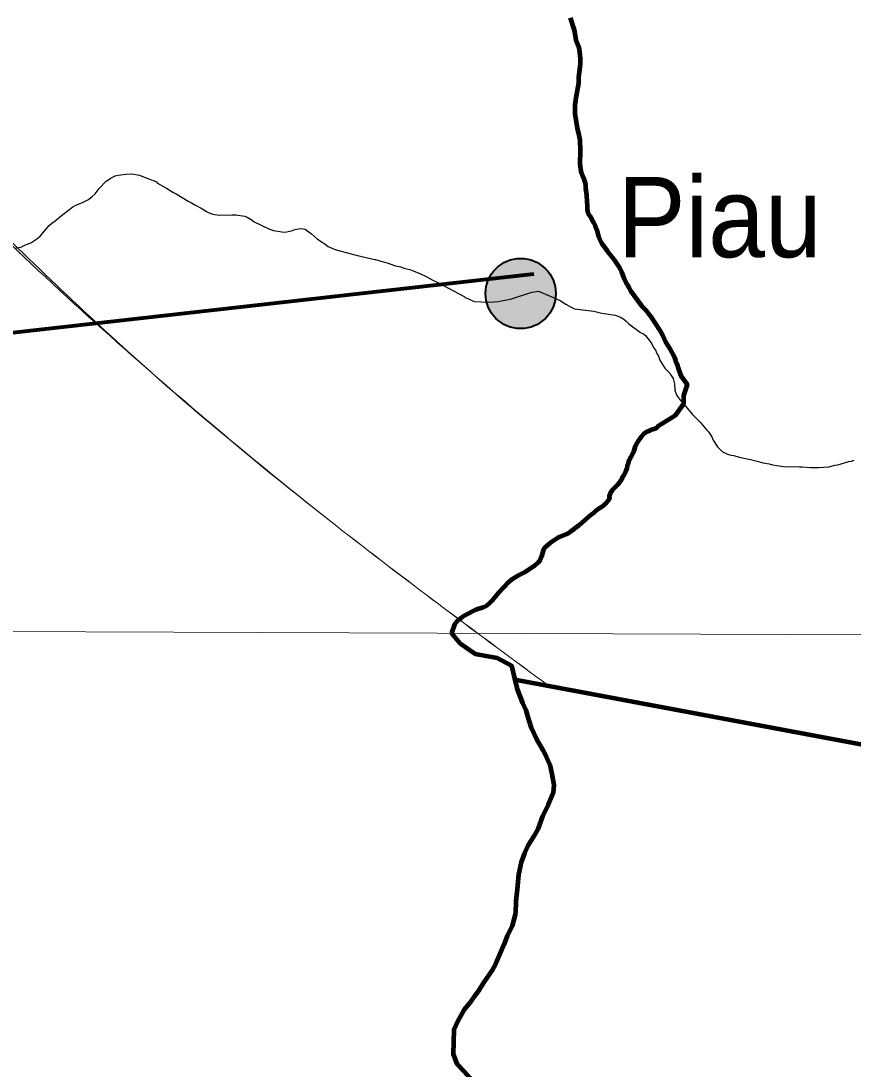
# Model space of a CAD drawing. Extents: x 553962 to 842807, y 8883888 to 9032388.
# Drawn here: x 642715 to 647901, y 8946863 to 8953394 of the extents above; entities that cross this region are included whole.
import ezdxf

# ---------------------------------------------------------------- set-up
doc = ezdxf.new("R2010")
doc.units = 0
doc.header["$LTSCALE"] = 200
doc.linetypes.add('DASH_DOUBLE_DOT', pattern=[9.2, 5, -1.2, 0.3, -1.2, 0.3, -1.2])
for name, color, linetype, lineweight in [('1', 7, 'Continuous', 13), ('11', 7, 'DASH_DOUBLE_DOT', 106), ('12', 7, 'Continuous', 25), ('24', 7, 'Continuous', 25), ('28', 7, 'Continuous', 40), ('41', 7, 'Continuous', 40), ('57', 7, 'Continuous', 13), ('9', 7, 'Continuous', 90)]:
    doc.layers.add(name, color=color, linetype=linetype, lineweight=lineweight)

msp = doc.modelspace()

# ---------------------------------------------------------------- hatches: boundary and pattern name
at = {"layer": '41'}
msp.add_hatch(color=256, dxfattribs=at).paths.add_polyline_path([(646048.1, 8951695.6, 1), (645610.5, 8951695.6, 1)])

# ---------------------------------------------------------------- linework, layer by layer
at = {"layer": '1'}
msp.add_line((565315.3, 8949866.8), (791497.7, 8949052.2), dxfattribs=at)
at = {"layer": '11'}
for points in [[(646137.1, 8953413.1), (646163.8, 8953336.6), (646173.3, 8953276.2), (646189.2, 8953237.6), (646194.5, 8953218.3), (646195.7, 8953199.1), (646201, 8953160.5), (646200.1, 8953124.6), (646189.3, 8953044.8), (646189.1, 8953005.5), (646173, 8952915), (646166.9, 8952872.1), (646167.8, 8952832.8), (646166.9, 8952813.5), (646183.8, 8952715.8), (646190.6, 8952691.8), (646197.6, 8952651.5), (646199.9, 8952587.2), (646199, 8952500.7), (646204.9, 8952458.4), (646221.6, 8952416.4), (646234, 8952374.3), (646233.3, 8952352.9), (646239.6, 8952309.2), (646240.8, 8952267.2), (646243.7, 8952245.8), (646242.9, 8952224.4), (646246, 8952203.9), (646250.1, 8952197.4), (646252.6, 8952188.8), (646256.5, 8952186.2), (646257.9, 8952182.2), (646261.2, 8952179.2), (646263.3, 8952172.7), (646263.3, 8952172.7)], [(646263.3, 8952172.7), (646267.7, 8952169.4), (646271.2, 8952159.2), (646283.8, 8952137.9), (646294.2, 8952117.2), (646303.6, 8952093.2), (646314.2, 8952051.4), (646322.1, 8952031.6), (646333.3, 8952009.5), (646371.8, 8951955.7), (646409.8, 8951910.5), (646439.8, 8951866.6), (646450.5, 8951847.3), (646458, 8951830.6), (646472.5, 8951791.1), (646486.6, 8951759.9), (646498.1, 8951747.5), (646499.4, 8951739.7), (646505.1, 8951731.6), (646514.5, 8951713), (646583.4, 8951618.5), (646609.2, 8951590.9), (646641.2, 8951551.7), (646693.7, 8951470.3), (646714.7, 8951432.5), (646733, 8951394), (646757.5, 8951355.4), (646787.6, 8951297.6), (646794.5, 8951277.6), (646802.9, 8951258.2), (646813.5, 8951223.4), (646828.6, 8951181.9), (646867.6, 8951129.6), (646843.9, 8951061.1), (646845, 8951008.9), (646791.1, 8950934.1), (646683.1, 8950866.1), (646677.6, 8950858.9), (646671.1, 8950853.6), (646653.5, 8950848.9), (646638.2, 8950843.1), (646630.5, 8950838.5), (646616.1, 8950832.7), (646599.8, 8950823.2), (646580.2, 8950802.2), (646561.5, 8950775.5), (646560.4, 8950771.5), (646555.5, 8950768.2), (646542.3, 8950744.3), (646531.8, 8950710), (646515, 8950677.7), (646512.5, 8950667.1), (646506.4, 8950657.3), (646501.5, 8950645.9), (646497.6, 8950630.7), (646492.6, 8950619.9), (646490.9, 8950607.9), (646484.9, 8950590.5), (646469.4, 8950559.1), (646462.5, 8950548.1), (646458, 8950536.5), (646432.8, 8950502.7), (646402.4, 8950473.1), (646389.6, 8950454.9), (646380.3, 8950433.1), (646383.9, 8950415.2), (646358.3, 8950385.9), (646349.6, 8950380.1), (646346.8, 8950375.3), (646301.4, 8950345.1), (646282.4, 8950327.6), (646263.6, 8950315.1), (646191.8, 8950251), (646140.7, 8950210.9), (646124.2, 8950199.9), (646066.5, 8950178.1), (646011.5, 8950140), (645996.7, 8950128.3), (645982.6, 8950114.3), (645972, 8950100.3), (645964.6, 8950078.7), (645959.7, 8950055.9), (645950.6, 8950035.7), (645935.3, 8950018), (645917.5, 8950001), (645852.5, 8949956.4), (645811.5, 8949936.1), (645770.2, 8949910.8), (645755.5, 8949898), (645724.3, 8949866.7), (645691.2, 8949830.5), (645653.7, 8949784.5), (645634.4, 8949765.2), (645614.7, 8949747.7), (645596.6, 8949739.8), (645549.2, 8949723.6), (645488.8, 8949693.4), (645467.8, 8949680.1), (645433.2, 8949653.7), (645415.9, 8949633.6), (645398.8, 8949579.9)], [(645398.8, 8949579.9), (645451.4, 8949513.8), (645546.2, 8949449.6), (645683.8, 8949425.1), (645771.3, 8949377.1), (645790.9, 8949299.5), (645808.1, 8949229.4), (645840.2, 8949144.1), (645862.5, 8949099), (645877.2, 8949041.4), (645894.5, 8948988.8), (645929.2, 8948913.5), (645968.9, 8948848.3), (645990.2, 8948804.6)], [(645990.2, 8948804.6), (646010.9, 8948758.1), (646021.2, 8948711.7), (646036.8, 8948634.2), (646031.6, 8948582.6), (646000.6, 8948510.3), (645964.4, 8948438), (645936.5, 8948358.1), (645911.3, 8948313.2), (645873.5, 8948253.4), (645853.2, 8948208.5), (645832.9, 8948151), (645815.1, 8948076.1), (645807.1, 8947983.6), (645799.2, 8947908.6), (645796.4, 8947834.9)], [(645796.4, 8947834.9), (645776, 8947756.1), (645745.7, 8947693.7), (645725.4, 8947636.3), (645695.1, 8947568.9), (645674.8, 8947521.4), (645649.6, 8947474), (645596.7, 8947399.3), (645571.5, 8947356.9), (645541.2, 8947317), (645511, 8947272.1), (645475.8, 8947229.8), (645437.9, 8947162.4), (645412.7, 8947110), (645409.8, 8947032.5), (645409.4, 8946954.9), (645431.6, 8946894.8), (645476.4, 8946847), (645541.1, 8946774.1), (645593.3, 8946706.3), (645643.1, 8946643.5), (645668.8, 8946601.4)]]:
    msp.add_lwpolyline(points, dxfattribs=at)
at = {"layer": '12'}
for points in [[(642676.8, 8951977.7), (642721, 8951987.2), (642724.8, 8951990.9), (642735.1, 8951994.5), (642743.5, 8952000), (642776.2, 8952012.3), (642776.2, 8952012.3), (642820.9, 8952041.1), (642834.6, 8952053), (642890.7, 8952119.2), (642906.7, 8952133.2), (642928.9, 8952148.8), (642967.9, 8952182.8), (642985, 8952193.5), (643037.1, 8952235.1), (643053.7, 8952245), (643102.2, 8952265.8), (643135, 8952282.2), (643159.6, 8952300.8), (643178.3, 8952317.8), (643202.9, 8952349.8), (643246, 8952395.7), (643257.2, 8952401.9), (643271.1, 8952413.3), (643302.7, 8952429.5), (643320.6, 8952432.8), (643369.3, 8952438.9), (643405.8, 8952441), (643454.6, 8952432.6), (643499.9, 8952415)], [(643499.9, 8952415), (643545.2, 8952397.3), (643559.2, 8952390.7), (643566.2, 8952384), (643622.9, 8952353.1), (643662.1, 8952326.2), (643681.9, 8952316.1), (643757.2, 8952271.2), (643777.1, 8952261.1), (643797.8, 8952247.5), (643838.2, 8952227.2), (643875.4, 8952204.5), (643892.2, 8952196.2), (643909.7, 8952190.3), (643950.5, 8952184.5), (644032, 8952186.5), (644053.2, 8952185.5), (644110.7, 8952177), (644118, 8952173), (644124.4, 8952171.9), (644149.9, 8952156.7), (644169.2, 8952143), (644206.8, 8952123.1), (644263.5, 8952096.7), (644288, 8952088.8), (644341, 8952079.2), (644360.9, 8952079), (644380.1, 8952081.2), (644401.4, 8952086.5), (644422.7, 8952094.8), (644444, 8952099.1), (644465.3, 8952100.1), (644485.8, 8952097), (644525.6, 8952067.7), (644562.3, 8952035.3), (644585, 8952018.8), (644610.2, 8952003.3), (644630.2, 8951989.1), (644666.2, 8951972.1), (644686.9, 8951965), (644764.8, 8951944.4), (644796.3, 8951937.1)], [(644796.3, 8951937.1), (644909.5, 8951910.6), (644920.9, 8951908.3), (644925, 8951908), (644979.4, 8951891), (644998, 8951886), (645049.9, 8951868.9), (645083.2, 8951861.5), (645101.9, 8951853.7), (645139.4, 8951844.3), (645159.2, 8951837.9), (645204.5, 8951819), (645240.2, 8951802.2), (645277.4, 8951781.6), (645324.7, 8951759), (645344.3, 8951747.1), (645476.8, 8951676.5), (645486.1, 8951668), (645499.5, 8951664.1), (645517.2, 8951655.3), (645535.4, 8951649), (645539.2, 8951646.5), (645633, 8951642.2), (645691.3, 8951646.6), (645709.7, 8951650.6), (645730.5, 8951653.2), (645766.4, 8951661.2), (645899.9, 8951704.4), (645939.9, 8951711), (645983.5, 8951692.1)], [(645983.5, 8951692.1), (646075.3, 8951652.5), (646111.1, 8951629), (646148, 8951608.5), (646165.6, 8951600.8), (646285, 8951585.6), (646336.2, 8951574), (646420.6, 8951561.2), (646455.4, 8951547.2), (646471.8, 8951536), (646471.8, 8951536), (646486.8, 8951523.3), (646503.8, 8951505.7), (646575.7, 8951452.5), (646594.5, 8951444.4), (646606.7, 8951433.2), (646637.1, 8951396.7), (646646.8, 8951381.7), (646658, 8951359.9), (646668.8, 8951343), (646678.2, 8951321.5), (646688, 8951304.6), (646697.6, 8951280.8), (646727.3, 8951231.4), (646758, 8951198.7), (646768, 8951185.4), (646778.9, 8951166.6), (646784.6, 8951148.8), (646787.7, 8951132.6), (646791.2, 8951093), (646800.1, 8951065.2), (646806.8, 8951054.1), (646825.7, 8951029.2), (646836.3, 8951019.3)], [(646836.3, 8951019.3), (646900.5, 8950941.1), (646947.8, 8950893.8), (646989, 8950843.2), (646999.3, 8950832.7), (647020.7, 8950801.7), (647029.2, 8950781.7), (647056, 8950740.5), (647082.1, 8950712.4), (647088.1, 8950711.7), (647092.4, 8950707.5), (647124.6, 8950692.9), (647140, 8950688.1), (647158.6, 8950685.3), (647192, 8950676), (647261.7, 8950661.8), (647311.3, 8950649.3), (647341.4, 8950639.7), (647378.7, 8950633.5), (647398.1, 8950627.8), (647482.5, 8950615.3), (647499.6, 8950617.1), (647516.6, 8950616.2), (647534.4, 8950617.1), (647567, 8950615.2), (647584.8, 8950616), (647635.2, 8950612), (647686.3, 8950610.9), (647752.8, 8950616), (647787.8, 8950625.3), (647806.4, 8950629), (647874.6, 8950648.1), (647891.6, 8950651.4), (647907.9, 8950657.4)]]:
    msp.add_lwpolyline(points, dxfattribs=at)
at = {"layer": '24', "lineweight": 53}
for points in [[(646137.1, 8953413.1), (646163.8, 8953336.6), (646173.3, 8953276.2), (646189.2, 8953237.6), (646194.5, 8953218.3), (646195.7, 8953199.1), (646201, 8953160.5), (646200.1, 8953124.6), (646189.3, 8953044.8), (646189.1, 8953005.5), (646173, 8952915), (646166.9, 8952872.1), (646167.8, 8952832.8), (646166.9, 8952813.5), (646183.8, 8952715.8), (646190.6, 8952691.8), (646197.6, 8952651.5), (646199.9, 8952587.2), (646199, 8952500.7), (646204.9, 8952458.4), (646221.6, 8952416.4), (646234, 8952374.3), (646233.3, 8952352.9), (646239.6, 8952309.2), (646240.8, 8952267.2), (646243.7, 8952245.8), (646242.9, 8952224.4), (646246, 8952203.9), (646250.1, 8952197.4), (646252.6, 8952188.8), (646256.5, 8952186.2), (646257.9, 8952182.2), (646261.2, 8952179.2), (646263.3, 8952172.7), (646263.3, 8952172.7)], [(646263.3, 8952172.7), (646267.7, 8952169.4), (646271.2, 8952159.2), (646283.8, 8952137.9), (646294.2, 8952117.2), (646303.6, 8952093.2), (646314.2, 8952051.4), (646322.1, 8952031.6), (646333.3, 8952009.5), (646371.8, 8951955.7), (646409.8, 8951910.5), (646439.8, 8951866.6), (646450.5, 8951847.3), (646458, 8951830.6), (646472.5, 8951791.1), (646486.6, 8951759.9), (646498.1, 8951747.5), (646499.4, 8951739.7), (646505.1, 8951731.6), (646514.5, 8951713), (646583.4, 8951618.5), (646609.2, 8951590.9), (646641.2, 8951551.7), (646693.7, 8951470.3), (646714.7, 8951432.5), (646733, 8951394), (646757.5, 8951355.4), (646787.6, 8951297.6), (646794.5, 8951277.6), (646802.9, 8951258.2), (646813.5, 8951223.4), (646828.6, 8951181.9), (646867.6, 8951129.6), (646843.9, 8951061.1), (646845, 8951008.9), (646791.1, 8950934.1), (646683.1, 8950866.1), (646677.6, 8950858.9), (646671.1, 8950853.6), (646653.5, 8950848.9), (646638.2, 8950843.1), (646630.5, 8950838.5), (646616.1, 8950832.7), (646599.8, 8950823.2), (646580.2, 8950802.2), (646561.5, 8950775.5), (646560.4, 8950771.5), (646555.5, 8950768.2), (646542.3, 8950744.3), (646531.8, 8950710), (646515, 8950677.7), (646512.5, 8950667.1), (646506.4, 8950657.3), (646501.5, 8950645.9), (646497.6, 8950630.7), (646492.6, 8950619.9), (646490.9, 8950607.9), (646484.9, 8950590.5), (646469.4, 8950559.1), (646462.5, 8950548.1), (646458, 8950536.5), (646432.8, 8950502.7), (646402.4, 8950473.1), (646389.6, 8950454.9), (646380.3, 8950433.1), (646383.9, 8950415.2), (646358.3, 8950385.9), (646349.6, 8950380.1), (646346.8, 8950375.3), (646301.4, 8950345.1), (646282.4, 8950327.6), (646263.6, 8950315.1), (646191.8, 8950251), (646140.7, 8950210.9), (646124.2, 8950199.9), (646066.5, 8950178.1), (646011.5, 8950140), (645996.7, 8950128.3), (645982.6, 8950114.3), (645972, 8950100.3), (645964.6, 8950078.7), (645959.7, 8950055.9), (645950.6, 8950035.7), (645935.3, 8950018), (645917.5, 8950001), (645852.5, 8949956.4), (645811.5, 8949936.1), (645770.2, 8949910.8), (645755.5, 8949898), (645724.3, 8949866.7), (645691.2, 8949830.5), (645653.7, 8949784.5), (645634.4, 8949765.2), (645614.7, 8949747.7), (645596.6, 8949739.8), (645549.2, 8949723.6), (645488.8, 8949693.4), (645467.8, 8949680.1), (645433.2, 8949653.7), (645415.9, 8949633.6), (645398.8, 8949579.9)], [(645398.8, 8949579.9), (645451.4, 8949513.8), (645546.2, 8949449.6), (645683.8, 8949425.1), (645771.3, 8949377.1), (645790.9, 8949299.5), (645808.1, 8949229.4), (645840.2, 8949144.1), (645862.5, 8949099), (645877.2, 8949041.4), (645894.5, 8948988.8), (645929.2, 8948913.5), (645968.9, 8948848.3), (645990.2, 8948804.6)], [(645990.2, 8948804.6), (646010.9, 8948758.1), (646021.2, 8948711.7), (646036.8, 8948634.2), (646031.6, 8948582.6), (646000.6, 8948510.3), (645964.4, 8948438), (645936.5, 8948358.1), (645911.3, 8948313.2), (645873.5, 8948253.4), (645853.2, 8948208.5), (645832.9, 8948151), (645815.1, 8948076.1), (645807.1, 8947983.6), (645799.2, 8947908.6), (645796.4, 8947834.9)], [(645796.4, 8947834.9), (645776, 8947756.1), (645745.7, 8947693.7), (645725.4, 8947636.3), (645695.1, 8947568.9), (645674.8, 8947521.4), (645649.6, 8947474), (645596.7, 8947399.3), (645571.5, 8947356.9), (645541.2, 8947317), (645511, 8947272.1), (645475.8, 8947229.8), (645437.9, 8947162.4), (645412.7, 8947110), (645409.8, 8947032.5), (645409.4, 8946954.9), (645431.6, 8946894.8), (645476.4, 8946847), (645541.1, 8946774.1), (645593.3, 8946706.3), (645643.1, 8946643.5), (645668.8, 8946601.4)]]:
    msp.add_lwpolyline(points, dxfattribs=at)
at = {"layer": '28', "lineweight": 80}
msp.add_line((628995.7, 8949921.6), (645912.1, 8951817.3), dxfattribs=at)
at = {"layer": '41'}
msp.add_circle((645829.3, 8951695.6), 218.8, dxfattribs=at)
at = {"layer": '57'}
msp.add_line((645793.1, 8949290.9), (646003, 8949251.6), dxfattribs=at)
msp.add_line((645793.1, 8949290.9), (646003, 8949251.6), dxfattribs=at)
for points in [[(645790.9, 8949299.5), (645808.1, 8949229.4), (645840.2, 8949144.1), (645862.5, 8949099), (645877.2, 8949041.4), (645894.5, 8948988.8), (645929.2, 8948913.5), (645968.9, 8948848.3), (645990.2, 8948804.6)], [(645796.4, 8947834.9), (645799.2, 8947908.6), (645807.1, 8947983.6), (645815.1, 8948076.1), (645832.9, 8948151), (645853.2, 8948208.5), (645873.5, 8948253.4), (645911.3, 8948313.2), (645936.5, 8948358.1), (645964.4, 8948438), (646000.6, 8948510.3), (646031.6, 8948582.6), (646036.8, 8948634.2), (646021.2, 8948711.7), (646010.9, 8948758.1), (645990.2, 8948804.6), (645968.9, 8948848.3), (645929.2, 8948913.5), (645894.5, 8948988.8), (645877.2, 8949041.4), (645862.5, 8949099), (645840.2, 8949144.1), (645808.1, 8949229.4), (645793, 8949290.8)], [(645796.4, 8947834.9), (645799.2, 8947908.6), (645807.1, 8947983.6), (645815.1, 8948076.1), (645832.9, 8948151), (645853.2, 8948208.5), (645873.5, 8948253.4), (645911.3, 8948313.2), (645936.5, 8948358.1), (645964.4, 8948438), (646000.6, 8948510.3), (646031.6, 8948582.6), (646036.8, 8948634.2), (646021.2, 8948711.7), (646010.9, 8948758.1), (645990.2, 8948804.6), (645968.9, 8948848.3), (645929.2, 8948913.5), (645894.5, 8948988.8), (645877.2, 8949041.4), (645862.5, 8949099), (645840.2, 8949144.1), (645808.1, 8949229.4), (645793, 8949290.8)], [(668185.2, 8933928.8), (662654, 8939737.7), (659002.1, 8941889), (653495.4, 8947850), (645793.1, 8949290.9)], [(645990.2, 8948804.6), (646010.9, 8948758.1), (646021.2, 8948711.7), (646036.8, 8948634.2), (646031.6, 8948582.6), (646000.6, 8948510.3), (645964.4, 8948438), (645936.5, 8948358.1), (645911.3, 8948313.2), (645873.5, 8948253.4), (645853.2, 8948208.5), (645832.9, 8948151), (645815.1, 8948076.1), (645807.1, 8947983.6), (645799.2, 8947908.6), (645796.4, 8947834.9)], [(645796.4, 8947834.9), (645776, 8947756.1), (645745.7, 8947693.7), (645725.4, 8947636.3), (645695.1, 8947568.9), (645674.8, 8947521.4), (645649.6, 8947474), (645596.7, 8947399.3), (645571.5, 8947356.9), (645541.2, 8947317), (645511, 8947272.1), (645475.8, 8947229.8), (645437.9, 8947162.4), (645412.7, 8947110), (645409.8, 8947032.5), (645409.4, 8946954.9), (645431.6, 8946894.8), (645476.4, 8946847), (645541.1, 8946774.1), (645593.3, 8946706.3), (645643.1, 8946643.5), (645668.8, 8946601.4)], [(645668.8, 8946601.4), (645643.1, 8946643.5), (645593.3, 8946706.3), (645541.1, 8946774.1), (645476.4, 8946847), (645431.6, 8946894.8), (645409.4, 8946954.9), (645409.8, 8947032.5), (645412.7, 8947110), (645437.9, 8947162.4), (645475.8, 8947229.8), (645511, 8947272.1), (645541.2, 8947317), (645571.5, 8947356.9), (645596.7, 8947399.3), (645649.6, 8947474), (645674.8, 8947521.4), (645695.1, 8947568.9), (645725.4, 8947636.3), (645745.7, 8947693.7), (645776, 8947756.1), (645796.4, 8947834.9)], [(645668.8, 8946601.4), (645643.1, 8946643.5), (645593.3, 8946706.3), (645541.1, 8946774.1), (645476.4, 8946847), (645431.6, 8946894.8), (645409.4, 8946954.9), (645409.8, 8947032.5), (645412.7, 8947110), (645437.9, 8947162.4), (645475.8, 8947229.8), (645511, 8947272.1), (645541.2, 8947317), (645571.5, 8947356.9), (645596.7, 8947399.3), (645649.6, 8947474), (645674.8, 8947521.4), (645695.1, 8947568.9), (645725.4, 8947636.3), (645745.7, 8947693.7), (645776, 8947756.1), (645796.4, 8947834.9)]]:
    msp.add_lwpolyline(points, dxfattribs=at)
for points in [[(646003, 8949251.6), (644721.9, 8950215.5), (643492.6, 8951234.6), (642099.6, 8952556.8), (640992.4, 8953664.6), (640171, 8954236.3), (637456.5, 8955772.9), (636135, 8956237.5), (634599.2, 8956630.6), (632599.1, 8956773.5), (629063.1, 8956702), (626348.7, 8956058.8), (623953.8, 8955209.7), (622371.6, 8954682.1), (620725.9, 8954192.9), (619183.7, 8953970.3), (617209.7, 8953965.7), (615658.4, 8954379), (614681.6, 8955057.1), (613704.6, 8955684.2), (612906.2, 8956374.2), (612068.3, 8956835.4), (609416.9, 8956401.3), (608625.2, 8956035.7), (607870.9, 8955517.4), (607396.1, 8954883.6), (607164, 8954388.6), (606950.6, 8954069.9)], [(646003, 8949251.6), (644721.9, 8950215.5), (643521.3, 8951208.7), (642428.2, 8952239.5), (641741.8, 8952914.9), (640407.4, 8954089.3), (638333.9, 8955336.1), (636237.3, 8956206.4), (633646.8, 8956732.8), (631365, 8956802.2), (629312, 8956729.1), (626793.2, 8956204.6), (623953.8, 8955209.7), (622371.6, 8954682.1), (620725.9, 8954192.9), (619183.7, 8953970.3), (617209.7, 8953965.7), (615658.4, 8954379), (614681.6, 8955057.1), (613704.6, 8955684.2), (612906.2, 8956374.2), (612068.3, 8956835.4), (609416.9, 8956401.3), (608625.2, 8956035.7), (607870.9, 8955517.4), (607396.1, 8954883.6), (607164, 8954388.6), (606950.6, 8954069.9)]]:
    msp.add_spline(points, degree=3, dxfattribs=at)
at = {"layer": '9'}
for points in [[(646137.1, 8953413.1), (646163.8, 8953336.6), (646173.3, 8953276.2), (646189.2, 8953237.6), (646194.5, 8953218.3), (646195.7, 8953199.1), (646201, 8953160.5), (646200.1, 8953124.6), (646189.3, 8953044.8), (646189.1, 8953005.5), (646173, 8952915), (646166.9, 8952872.1), (646167.8, 8952832.8), (646166.9, 8952813.5), (646183.8, 8952715.8), (646190.6, 8952691.8), (646197.6, 8952651.5), (646199.9, 8952587.2), (646199, 8952500.7), (646204.9, 8952458.4), (646221.6, 8952416.4), (646234, 8952374.3), (646233.3, 8952352.9), (646239.6, 8952309.2), (646240.8, 8952267.2), (646243.7, 8952245.8), (646242.9, 8952224.4), (646246, 8952203.9), (646250.1, 8952197.4), (646252.6, 8952188.8), (646256.5, 8952186.2), (646257.9, 8952182.2), (646261.2, 8952179.2), (646263.3, 8952172.7), (646263.3, 8952172.7)], [(646263.3, 8952172.7), (646267.7, 8952169.4), (646271.2, 8952159.2), (646283.8, 8952137.9), (646294.2, 8952117.2), (646303.6, 8952093.2), (646314.2, 8952051.4), (646322.1, 8952031.6), (646333.3, 8952009.5), (646371.8, 8951955.7), (646409.8, 8951910.5), (646439.8, 8951866.6), (646450.5, 8951847.3), (646458, 8951830.6), (646472.5, 8951791.1), (646486.6, 8951759.9), (646498.1, 8951747.5), (646499.4, 8951739.7), (646505.1, 8951731.6), (646514.5, 8951713), (646583.4, 8951618.5), (646609.2, 8951590.9), (646641.2, 8951551.7), (646693.7, 8951470.3), (646714.7, 8951432.5), (646733, 8951394), (646757.5, 8951355.4), (646787.6, 8951297.6), (646794.5, 8951277.6), (646802.9, 8951258.2), (646813.5, 8951223.4), (646828.6, 8951181.9), (646867.6, 8951129.6), (646843.9, 8951061.1), (646845, 8951008.9), (646791.1, 8950934.1), (646683.1, 8950866.1), (646677.6, 8950858.9), (646671.1, 8950853.6), (646653.5, 8950848.9), (646638.2, 8950843.1), (646630.5, 8950838.5), (646616.1, 8950832.7), (646599.8, 8950823.2), (646580.2, 8950802.2), (646561.5, 8950775.5), (646560.4, 8950771.5), (646555.5, 8950768.2), (646542.3, 8950744.3), (646531.8, 8950710), (646515, 8950677.7), (646512.5, 8950667.1), (646506.4, 8950657.3), (646501.5, 8950645.9), (646497.6, 8950630.7), (646492.6, 8950619.9), (646490.9, 8950607.9), (646484.9, 8950590.5), (646469.4, 8950559.1), (646462.5, 8950548.1), (646458, 8950536.5), (646432.8, 8950502.7), (646402.4, 8950473.1), (646389.6, 8950454.9), (646380.3, 8950433.1), (646383.9, 8950415.2), (646358.3, 8950385.9), (646349.6, 8950380.1), (646346.8, 8950375.3), (646301.4, 8950345.1), (646282.4, 8950327.6), (646263.6, 8950315.1), (646191.8, 8950251), (646140.7, 8950210.9), (646124.2, 8950199.9), (646066.5, 8950178.1), (646011.5, 8950140), (645996.7, 8950128.3), (645982.6, 8950114.3), (645972, 8950100.3), (645964.6, 8950078.7), (645959.7, 8950055.9), (645950.6, 8950035.7), (645935.3, 8950018), (645917.5, 8950001), (645852.5, 8949956.4), (645811.5, 8949936.1), (645770.2, 8949910.8), (645755.5, 8949898), (645724.3, 8949866.7), (645691.2, 8949830.5), (645653.7, 8949784.5), (645634.4, 8949765.2), (645614.7, 8949747.7), (645596.6, 8949739.8), (645549.2, 8949723.6), (645488.8, 8949693.4), (645467.8, 8949680.1), (645433.2, 8949653.7), (645415.9, 8949633.6), (645398.8, 8949579.9)], [(645398.8, 8949579.9), (645451.4, 8949513.8), (645546.2, 8949449.6), (645683.8, 8949425.1), (645771.3, 8949377.1), (645790.9, 8949299.5), (645808.1, 8949229.4), (645840.2, 8949144.1), (645862.5, 8949099), (645877.2, 8949041.4), (645894.5, 8948988.8), (645929.2, 8948913.5), (645968.9, 8948848.3), (645990.2, 8948804.6)], [(645793.1, 8949290.9), (653495.4, 8947850), (659002.1, 8941889), (662654, 8939737.7), (668185.2, 8933928.8)], [(645990.2, 8948804.6), (646010.9, 8948758.1), (646021.2, 8948711.7), (646036.8, 8948634.2), (646031.6, 8948582.6), (646000.6, 8948510.3), (645964.4, 8948438), (645936.5, 8948358.1), (645911.3, 8948313.2), (645873.5, 8948253.4), (645853.2, 8948208.5), (645832.9, 8948151), (645815.1, 8948076.1), (645807.1, 8947983.6), (645799.2, 8947908.6), (645796.4, 8947834.9)], [(645796.4, 8947834.9), (645776, 8947756.1), (645745.7, 8947693.7), (645725.4, 8947636.3), (645695.1, 8947568.9), (645674.8, 8947521.4), (645649.6, 8947474), (645596.7, 8947399.3), (645571.5, 8947356.9), (645541.2, 8947317), (645511, 8947272.1), (645475.8, 8947229.8), (645437.9, 8947162.4), (645412.7, 8947110), (645409.8, 8947032.5), (645409.4, 8946954.9), (645431.6, 8946894.8), (645476.4, 8946847), (645541.1, 8946774.1), (645593.3, 8946706.3), (645643.1, 8946643.5), (645668.8, 8946601.4)]]:
    msp.add_lwpolyline(points, dxfattribs=at)
msp.add_spline([(637260.6, 8972975.8), (641524.5, 8971056.2), (652526.1, 8965412.7), (653164.3, 8965062.8), (670790.5, 8953770.1), (686194, 8943929.9), (696283.3, 8937647.1)], degree=3, dxfattribs=at)

# ---------------------------------------------------------------- texts
at = {"layer": '41', "width": 0.95}
msp.add_text('Piau', height=500, dxfattribs=at).set_placement((646433.5, 8951921.7))

doc.saveas('drawing.dxf')
